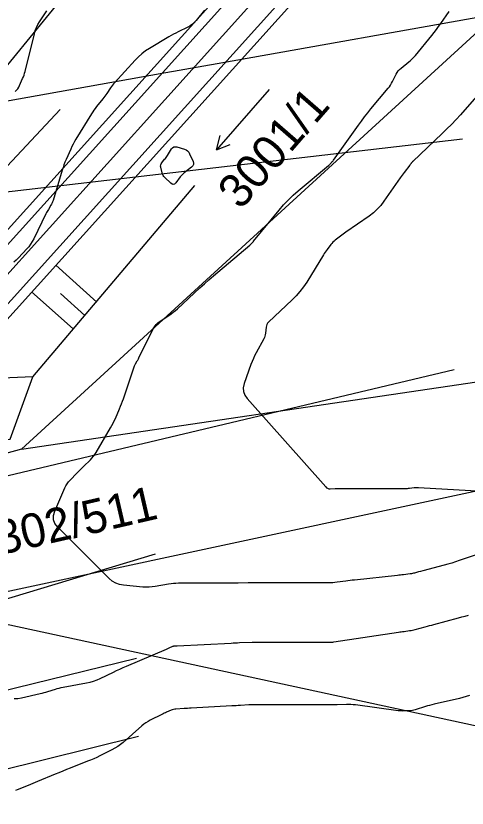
# Model space of a CAD drawing. Extents: x -534481 to -534262, y -1190577 to -1190138.
# Drawn here: x -534401.7 to -534390.37, y -1190524.99 to -1190505.1 of the extents above; entities that cross this region are included whole.
import ezdxf

# ---------------------------------------------------------------- set-up
doc = ezdxf.new("R2010")
doc.units = 0
for name, color, linetype in [('Bonity', 7, 'Continuous'), ('Definiční body', 7, 'Continuous'), ('Polygon budovy', 7, 'Continuous'), ('Vrstva 18', 7, 'Continuous'), ('Vrstva 19', 7, 'Continuous'), ('Vrstva 31', 7, 'Continuous'), ('Vrstva 35', 7, 'Continuous'), ('Vrstva 36', 7, 'Continuous'), ('Vrstva 48', 7, 'Continuous'), ('Vrstva 58', 7, 'Continuous'), ('Značky bodu BP', 7, 'Continuous')]:
    doc.layers.add(name, color=color, linetype=linetype)

msp = doc.modelspace()

# ---------------------------------------------------------------- linework, layer by layer
at = {"layer": 'Bonity'}
msp.add_line((-534422.24, -1190529.075), (-534398.624, -1190523.185), dxfattribs=at)
msp.add_lwpolyline([(-534408.105, -1190518.46), (-534393.616, -1190502.389), (-534391.346, -1190496.962), (-534392.763, -1190488.017), (-534396.655, -1190477.752), (-534402.513, -1190464.283), (-534404.757, -1190456.741), (-534408.311, -1190433.088), (-534409.248, -1190427.879), (-534409.316, -1190416.054), (-534409.076, -1190409.418), (-534409.868, -1190391.439)], dxfattribs=at)
at = {"layer": 'Definiční body'}
for p, q in [((-534402.95, -1190507.61), (-534395.53, -1190498.55)), ((-534389.63, -1190505.06), (-534401.56, -1190515.98)), ((-534401.56, -1190515.98), (-534378.386, -1190512.549))]:
    msp.add_line(p, q, dxfattribs=at)
for points in [[(-534389.63, -1190505.06), (-534396.5, -1190506.28), (-534398.08, -1190506.56), (-534402.44, -1190507.34), (-534402.95, -1190507.61)], [(-534378.833, -1190515.085), (-534383.27, -1190515.56), (-534409.16, -1190521.11), (-534410.57, -1190521.41), (-534422.34, -1190523.93)], [(-534401.56, -1190515.98), (-534406.2, -1190517.26), (-534407.55, -1190517.63), (-534412.19, -1190518.9)]]:
    msp.add_lwpolyline(points, dxfattribs=at)
at = {"layer": 'Vrstva 18'}
for points in [[(-534401.716, -1190507.007), (-534401.683, -1190506.973), (-534401.653, -1190506.937), (-534401.628, -1190506.897), (-534401.606, -1190506.855), (-534401.529, -1190506.679), (-534401.511, -1190506.635), (-534401.494, -1190506.59), (-534401.48, -1190506.545), (-534401.467, -1190506.499), (-534401.234, -1190505.552), (-534401.211, -1190505.474), (-534401.182, -1190505.399), (-534401.146, -1190505.326), (-534401.104, -1190505.256), (-534400.924, -1190504.982)], [(-534389.898, -1190506.863), (-534390.536, -1190507.586), (-534390.647, -1190507.708), (-534390.76, -1190507.828), (-534390.875, -1190507.945), (-534390.994, -1190508.06), (-534391.733, -1190508.758), (-534391.738, -1190508.763), (-534391.743, -1190508.768), (-534391.747, -1190508.773), (-534391.752, -1190508.778), (-534391.771, -1190508.801), (-534391.778, -1190508.809), (-534391.785, -1190508.818), (-534391.801, -1190508.84), (-534391.811, -1190508.853), (-534391.953, -1190509.04), (-534391.978, -1190509.072), (-534392.002, -1190509.105), (-534392.026, -1190509.138), (-534392.05, -1190509.172), (-534392.458, -1190509.76), (-534392.538, -1190509.865), (-534392.626, -1190509.961), (-534392.723, -1190510.05), (-534392.828, -1190510.13), (-534393.416, -1190510.538), (-534393.449, -1190510.561), (-534393.482, -1190510.585), (-534393.515, -1190510.609), (-534393.548, -1190510.634), (-534393.68, -1190510.735), (-534393.711, -1190510.76), (-534393.739, -1190510.787), (-534393.766, -1190510.816), (-534393.791, -1190510.847), (-534393.887, -1190510.973), (-534393.911, -1190511.005), (-534393.934, -1190511.038), (-534393.956, -1190511.071), (-534393.977, -1190511.104), (-534394.398, -1190511.786), (-534394.479, -1190511.907), (-534394.567, -1190512.023), (-534394.663, -1190512.133), (-534394.766, -1190512.237), (-534395.353, -1190512.792), (-534395.378, -1190512.82), (-534395.397, -1190512.85), (-534395.41, -1190512.884), (-534395.417, -1190512.92), (-534395.432, -1190513.072), (-534395.437, -1190513.11), (-534395.447, -1190513.146), (-534395.459, -1190513.181), (-534395.476, -1190513.215), (-534395.667, -1190513.568), (-534395.704, -1190513.638), (-534395.737, -1190513.71), (-534395.768, -1190513.783), (-534395.796, -1190513.858), (-534395.966, -1190514.337), (-534395.99, -1190514.439), (-534395.985, -1190514.536), (-534395.953, -1190514.627), (-534395.893, -1190514.713), (-534393.919, -1190516.93), (-534393.897, -1190516.951), (-534393.871, -1190516.965), (-534393.843, -1190516.974), (-534393.812, -1190516.975), (-534393.684, -1190516.97), (-534393.652, -1190516.969), (-534393.62, -1190516.969), (-534393.588, -1190516.968), (-534393.555, -1190516.968), (-534391.922, -1190516.968), (-534391.894, -1190516.967), (-534391.867, -1190516.966), (-534391.839, -1190516.964), (-534391.812, -1190516.961), (-534391.702, -1190516.947), (-534391.675, -1190516.944), (-534391.647, -1190516.943), (-534391.62, -1190516.942), (-534391.592, -1190516.943), (-534389.984, -1190517.034)], [(-534401.742, -1190522.239), (-534401.649, -1190522.237), (-534401.555, -1190522.222), (-534401.089, -1190522.116), (-534401.041, -1190522.104), (-534400.993, -1190522.092), (-534400.945, -1190522.078), (-534400.897, -1190522.064), (-534400.707, -1190522.005), (-534400.659, -1190521.991), (-534400.611, -1190521.978), (-534400.563, -1190521.967), (-534400.514, -1190521.957), (-534399.922, -1190521.849), (-534399.833, -1190521.829), (-534399.747, -1190521.804), (-534399.662, -1190521.773), (-534399.579, -1190521.737), (-534399.251, -1190521.579), (-534399.169, -1190521.54), (-534399.087, -1190521.502), (-534399.004, -1190521.465), (-534398.92, -1190521.429), (-534397.919, -1190521), (-534397.901, -1190520.993), (-534397.884, -1190520.985), (-534397.866, -1190520.977), (-534397.849, -1190520.969), (-534397.76, -1190520.93), (-534397.751, -1190520.926), (-534397.743, -1190520.924), (-534397.734, -1190520.922), (-534397.725, -1190520.921), (-534397.66, -1190520.918), (-534397.651, -1190520.917), (-534396.295, -1190520.85), (-534396.242, -1190520.847), (-534396.189, -1190520.845), (-534396.136, -1190520.842), (-534396.082, -1190520.839), (-534395.769, -1190520.824), (-534395.758, -1190520.824), (-534395.738, -1190520.824), (-534393.749, -1190520.824), (-534393.74, -1190520.823), (-534393.716, -1190520.82), (-534393.713, -1190520.82), (-534392.094, -1190520.574), (-534392.059, -1190520.569), (-534392.024, -1190520.564), (-534391.989, -1190520.56), (-534391.954, -1190520.555), (-534391.813, -1190520.537), (-534391.778, -1190520.532), (-534391.744, -1190520.526), (-534391.709, -1190520.519), (-534391.675, -1190520.51), (-534391.419, -1190520.442), (-534391.365, -1190520.427), (-534391.311, -1190520.412), (-534391.257, -1190520.398), (-534391.203, -1190520.383), (-534390.585, -1190520.216), (-534390.501, -1190520.193), (-534390.417, -1190520.171), (-534390.333, -1190520.148)]]:
    msp.add_lwpolyline(points, dxfattribs=at)
msp.add_lwpolyline([(-534397.715, -1190509.328), (-534397.746, -1190509.339), (-534397.777, -1190509.333), (-534397.811, -1190509.309), (-534397.963, -1190509.162), (-534397.986, -1190509.137), (-534398.004, -1190509.109), (-534398.018, -1190509.079), (-534398.028, -1190509.047), (-534398.06, -1190508.902), (-534398.064, -1190508.874), (-534398.061, -1190508.847), (-534398.052, -1190508.822), (-534398.037, -1190508.798), (-534397.964, -1190508.706), (-534397.946, -1190508.683), (-534397.929, -1190508.659), (-534397.912, -1190508.635), (-534397.896, -1190508.61), (-534397.789, -1190508.444), (-534397.764, -1190508.414), (-534397.734, -1190508.396), (-534397.7, -1190508.39), (-534397.661, -1190508.396), (-534397.468, -1190508.452), (-534397.426, -1190508.469), (-534397.39, -1190508.493), (-534397.36, -1190508.525), (-534397.337, -1190508.565), (-534397.25, -1190508.758), (-534397.238, -1190508.799), (-534397.24, -1190508.837), (-534397.256, -1190508.871), (-534397.287, -1190508.902), (-534397.438, -1190509.017), (-534397.475, -1190509.047), (-534397.509, -1190509.079), (-534397.541, -1190509.113), (-534397.571, -1190509.149), (-534397.686, -1190509.3)], close=True, dxfattribs=at)
at = {"layer": 'Vrstva 19'}
for points in [[(-534396.966, -1190504.966), (-534397.175, -1190505.224), (-534397.219, -1190505.273), (-534397.268, -1190505.317), (-534397.322, -1190505.355), (-534397.38, -1190505.388), (-534397.622, -1190505.506), (-534397.682, -1190505.536), (-534397.742, -1190505.567), (-534397.801, -1190505.6), (-534397.859, -1190505.634), (-534398.343, -1190505.924), (-534398.441, -1190505.987), (-534398.533, -1190506.057), (-534398.62, -1190506.133), (-534398.701, -1190506.216), (-534399.222, -1190506.783), (-534399.25, -1190506.814), (-534399.276, -1190506.846), (-534399.301, -1190506.88), (-534399.325, -1190506.914), (-534399.418, -1190507.053), (-534399.442, -1190507.088), (-534399.466, -1190507.122), (-534399.491, -1190507.155), (-534399.517, -1190507.188), (-534399.674, -1190507.383), (-534399.708, -1190507.427), (-534399.74, -1190507.472), (-534399.771, -1190507.518), (-534399.801, -1190507.565), (-534400.19, -1190508.201), (-534400.227, -1190508.262), (-534400.261, -1190508.325), (-534400.293, -1190508.388), (-534400.323, -1190508.453), (-534400.438, -1190508.714), (-534400.466, -1190508.78), (-534400.491, -1190508.846), (-534400.515, -1190508.913), (-534400.537, -1190508.981), (-534400.767, -1190509.743), (-534400.777, -1190509.772), (-534400.789, -1190509.801), (-534400.802, -1190509.829), (-534400.818, -1190509.856), (-534400.883, -1190509.963), (-534400.899, -1190509.99), (-534400.914, -1190510.017), (-534400.929, -1190510.045), (-534400.943, -1190510.073), (-534401.251, -1190510.705), (-534401.288, -1190510.773), (-534401.329, -1190510.838), (-534401.375, -1190510.899), (-534401.425, -1190510.957), (-534401.637, -1190511.183), (-534401.691, -1190511.239), (-534401.747, -1190511.292)], [(-534390.065, -1190518.606), (-534390.567, -1190518.78), (-534390.662, -1190518.811), (-534390.757, -1190518.841), (-534390.852, -1190518.869), (-534390.948, -1190518.895), (-534391.485, -1190519.038), (-534391.536, -1190519.051), (-534391.588, -1190519.065), (-534391.691, -1190519.093), (-534391.717, -1190519.099), (-534391.743, -1190519.105), (-534391.77, -1190519.11), (-534391.796, -1190519.114), (-534391.968, -1190519.135), (-534392.006, -1190519.14), (-534392.043, -1190519.144), (-534392.081, -1190519.149), (-534392.119, -1190519.153), (-534393.199, -1190519.268), (-534393.253, -1190519.274), (-534393.308, -1190519.281), (-534393.362, -1190519.287), (-534393.417, -1190519.294), (-534393.634, -1190519.323), (-534393.689, -1190519.329), (-534393.743, -1190519.334), (-534393.798, -1190519.336), (-534393.853, -1190519.337), (-534395.617, -1190519.337), (-534395.68, -1190519.337), (-534395.743, -1190519.338), (-534395.806, -1190519.339), (-534395.869, -1190519.34), (-534396.121, -1190519.345), (-534396.183, -1190519.346), (-534396.246, -1190519.347), (-534396.309, -1190519.347), (-534396.372, -1190519.347), (-534397.121, -1190519.343), (-534397.184, -1190519.342), (-534397.246, -1190519.343), (-534397.308, -1190519.343), (-534397.37, -1190519.345), (-534397.619, -1190519.35), (-534397.681, -1190519.352), (-534397.743, -1190519.357), (-534397.804, -1190519.364), (-534397.866, -1190519.374), (-534398.202, -1190519.431), (-534398.279, -1190519.441), (-534398.356, -1190519.447), (-534398.433, -1190519.447), (-534398.51, -1190519.443), (-534398.994, -1190519.399), (-534399.097, -1190519.382), (-534399.192, -1190519.347), (-534399.279, -1190519.296), (-534399.359, -1190519.229), (-534400.645, -1190517.942), (-534400.717, -1190517.85), (-534400.753, -1190517.752), (-534400.755, -1190517.646), (-534400.722, -1190517.535), (-534400.469, -1190516.954), (-534400.443, -1190516.901), (-534400.412, -1190516.85), (-534400.377, -1190516.803), (-534400.337, -1190516.758), (-534400.171, -1190516.586), (-534400.129, -1190516.543), (-534400.087, -1190516.501), (-534400.044, -1190516.459), (-534400.001, -1190516.417), (-534399.829, -1190516.25), (-534399.788, -1190516.207), (-534399.749, -1190516.162), (-534399.714, -1190516.114), (-534399.682, -1190516.063), (-534399.322, -1190515.448), (-534399.289, -1190515.39), (-534399.258, -1190515.332), (-534399.229, -1190515.272), (-534399.201, -1190515.211), (-534399.096, -1190514.967), (-534399.07, -1190514.905), (-534399.045, -1190514.844), (-534399.022, -1190514.781), (-534399, -1190514.718), (-534398.727, -1190513.914), (-534398.72, -1190513.894), (-534398.711, -1190513.875), (-534398.702, -1190513.857), (-534398.692, -1190513.838), (-534398.65, -1190513.766), (-534398.64, -1190513.748), (-534398.629, -1190513.73), (-534398.62, -1190513.711), (-534398.61, -1190513.693), (-534398.252, -1190512.965), (-534398.219, -1190512.908), (-534398.179, -1190512.856), (-534398.133, -1190512.811), (-534398.08, -1190512.771), (-534397.855, -1190512.624), (-534397.8, -1190512.586), (-534397.747, -1190512.546), (-534397.695, -1190512.504), (-534397.645, -1190512.46), (-534397.079, -1190511.936), (-534396.967, -1190511.834), (-534396.855, -1190511.733), (-534396.741, -1190511.634), (-534396.626, -1190511.536), (-534395.824, -1190510.859), (-534395.816, -1190510.852), (-534395.808, -1190510.844), (-534395.799, -1190510.836), (-534395.791, -1190510.829), (-534395.759, -1190510.797), (-534395.751, -1190510.789), (-534395.744, -1190510.78), (-534395.736, -1190510.772), (-534395.729, -1190510.763), (-534395.086, -1190509.98), (-534394.976, -1190509.851), (-534394.86, -1190509.728), (-534394.738, -1190509.61), (-534394.61, -1190509.499), (-534393.852, -1190508.864), (-534393.84, -1190508.854), (-534393.828, -1190508.844), (-534393.817, -1190508.833), (-534393.807, -1190508.822), (-534393.764, -1190508.777), (-534393.754, -1190508.765), (-534393.744, -1190508.753), (-534393.734, -1190508.741), (-534393.725, -1190508.729), (-534393.099, -1190507.849), (-534393.023, -1190507.745), (-534392.945, -1190507.642), (-534392.865, -1190507.54), (-534392.783, -1190507.44), (-534392.352, -1190506.923), (-534392.321, -1190506.883), (-534392.292, -1190506.841), (-534392.266, -1190506.798), (-534392.242, -1190506.753), (-534392.153, -1190506.57), (-534392.129, -1190506.526), (-534392.1, -1190506.486), (-534392.067, -1190506.449), (-534392.029, -1190506.416), (-534391.835, -1190506.263), (-534391.79, -1190506.226), (-534391.748, -1190506.186), (-534391.707, -1190506.145), (-534391.669, -1190506.101), (-534391.253, -1190505.595), (-534391.195, -1190505.523), (-534391.139, -1190505.45), (-534391.084, -1190505.375), (-534391.031, -1190505.3), (-534390.821, -1190504.996)], [(-534390.309, -1190522.164), (-534390.392, -1190522.192), (-534390.475, -1190522.216), (-534390.559, -1190522.237), (-534391.2, -1190522.386), (-534391.255, -1190522.399), (-534391.31, -1190522.414), (-534391.364, -1190522.429), (-534391.418, -1190522.446), (-534391.674, -1190522.526), (-534391.709, -1190522.535), (-534391.744, -1190522.542), (-534391.779, -1190522.547), (-534391.815, -1190522.549), (-534391.959, -1190522.554), (-534391.995, -1190522.555), (-534392.031, -1190522.554), (-534392.067, -1190522.551), (-534392.102, -1190522.547), (-534393.173, -1190522.403), (-534393.23, -1190522.396), (-534393.286, -1190522.392), (-534393.343, -1190522.39), (-534393.4, -1190522.39), (-534393.629, -1190522.396), (-534393.686, -1190522.397), (-534393.743, -1190522.398), (-534393.8, -1190522.398), (-534393.857, -1190522.399), (-534395.637, -1190522.399), (-534395.69, -1190522.399), (-534395.743, -1190522.4), (-534395.796, -1190522.402), (-534395.849, -1190522.404), (-534396.061, -1190522.415), (-534396.114, -1190522.418), (-534396.167, -1190522.421), (-534396.22, -1190522.424), (-534396.273, -1190522.427), (-534397.299, -1190522.484), (-534397.343, -1190522.487), (-534397.388, -1190522.489), (-534397.432, -1190522.492), (-534397.477, -1190522.494), (-534397.68, -1190522.505), (-534397.711, -1190522.508), (-534397.742, -1190522.514), (-534397.772, -1190522.522), (-534397.801, -1190522.534), (-534397.917, -1190522.586), (-534397.946, -1190522.599), (-534397.975, -1190522.613), (-534398.004, -1190522.626), (-534398.033, -1190522.641), (-534398.325, -1190522.786), (-534398.381, -1190522.817), (-534398.436, -1190522.851), (-534398.488, -1190522.889), (-534398.538, -1190522.93), (-534399.006, -1190523.342), (-534399.071, -1190523.396), (-534399.14, -1190523.445), (-534399.211, -1190523.49), (-534399.286, -1190523.53), (-534399.591, -1190523.681), (-534399.667, -1190523.718), (-534399.745, -1190523.753), (-534399.823, -1190523.786), (-534399.901, -1190523.818), (-534400.335, -1190523.989), (-534400.429, -1190524.027), (-534400.523, -1190524.065), (-534400.617, -1190524.103), (-534400.711, -1190524.142), (-534401.157, -1190524.327), (-534401.216, -1190524.351), (-534401.274, -1190524.375), (-534401.333, -1190524.399), (-534401.391, -1190524.423), (-534401.669, -1190524.536), (-534401.706, -1190524.549)]]:
    msp.add_lwpolyline(points, dxfattribs=at)
at = {"layer": 'Vrstva 31'}
msp.add_line((-534405.492, -1190519.605), (-534380.58, -1190524.995), dxfattribs=at)
at = {"layer": 'Vrstva 35'}
for p, q in [((-534407.09, -1190514.42), (-534400.591, -1190507.452)), ((-534416.715, -1190511.238), (-534390.485, -1190508.189)), ((-534401.27, -1190514.17), (-534397.206, -1190509.36)), ((-534398.2, -1190518.62), (-534407.09, -1190521.3))]:
    msp.add_line(p, q, dxfattribs=at)
for points in [[(-534405.407, -1190514.348), (-534394.258, -1190501.982), (-534392.12, -1190496.869), (-534393.492, -1190488.211), (-534397.35, -1190478.035), (-534403.219, -1190464.54), (-534405.491, -1190456.905), (-534409.051, -1190433.21), (-534409.998, -1190427.948), (-534410.066, -1190416.042), (-534409.827, -1190409.421), (-534410.645, -1190390.84)], [(-534405.057, -1190514.333), (-534394.044, -1190502.118), (-534391.862, -1190496.9), (-534393.249, -1190488.146), (-534397.118, -1190477.94), (-534402.983, -1190464.455), (-534405.247, -1190456.85), (-534408.804, -1190433.17), (-534409.748, -1190427.925), (-534409.816, -1190416.046), (-534409.577, -1190409.42), (-534410.397, -1190390.795)], [(-534403.656, -1190514.273), (-534393.187, -1190502.661), (-534390.83, -1190497.024), (-534392.278, -1190487.888), (-534396.191, -1190477.563), (-534402.042, -1190464.111), (-534404.268, -1190456.632), (-534407.818, -1190433.007), (-534408.749, -1190427.833), (-534408.816, -1190416.061), (-534408.576, -1190409.416), (-534409.363, -1190391.537)], [(-534403.306, -1190514.257), (-534392.973, -1190502.796), (-534390.572, -1190497.055), (-534392.035, -1190487.824), (-534395.96, -1190477.469), (-534401.807, -1190464.025), (-534404.023, -1190456.578), (-534407.571, -1190432.966), (-534408.499, -1190427.81), (-534408.566, -1190416.065), (-534408.326, -1190409.415), (-534409.111, -1190391.586)], [(-534422.71, -1190527.13), (-534410.3, -1190523.97), (-534409.53, -1190523.89), (-534398.67, -1190521.23)]]:
    msp.add_lwpolyline(points, dxfattribs=at)
at = {"layer": 'Vrstva 36'}
for p, q in [((-534399.665, -1190512.289), (-534400.7, -1190511.367)), ((-534400.264, -1190512.961), (-534401.303, -1190512.035)), ((-534399.965, -1190512.625), (-534400.582, -1190512.075))]:
    msp.add_line(p, q, dxfattribs=at)
at = {"layer": 'Vrstva 48'}
for p, q in [((-534395.341, -1190506.951), (-534396.66, -1190508.468)), ((-534396.66, -1190508.468), (-534396.572, -1190508.11)), ((-534396.66, -1190508.468), (-534396.318, -1190508.331))]:
    msp.add_line(p, q, dxfattribs=at)
at = {"layer": 'Vrstva 58'}
msp.add_lwpolyline([(-534420.706, -1190521.11), (-534390.696, -1190513.981)], dxfattribs=at)
at = {"layer": 'Značky bodu BP'}
msp.add_lwpolyline([(-534407.09, -1190514.42), (-534407.09, -1190514.42), (-534407.95, -1190515.91), (-534401.84, -1190515.73), (-534401.27, -1190514.17), (-534407.09, -1190514.42)], dxfattribs=at)

# ---------------------------------------------------------------- texts
at = {"layer": 'Polygon budovy'}
for s, rotation, p in [('3001/1', 49, (-534396.057, -1190509.998)), ('2302/511', 13, (-534402.712, -1190518.785))]:
    msp.add_text(s, height=0.85, rotation=rotation, dxfattribs=at).set_placement(p)

doc.saveas('drawing.dxf')
